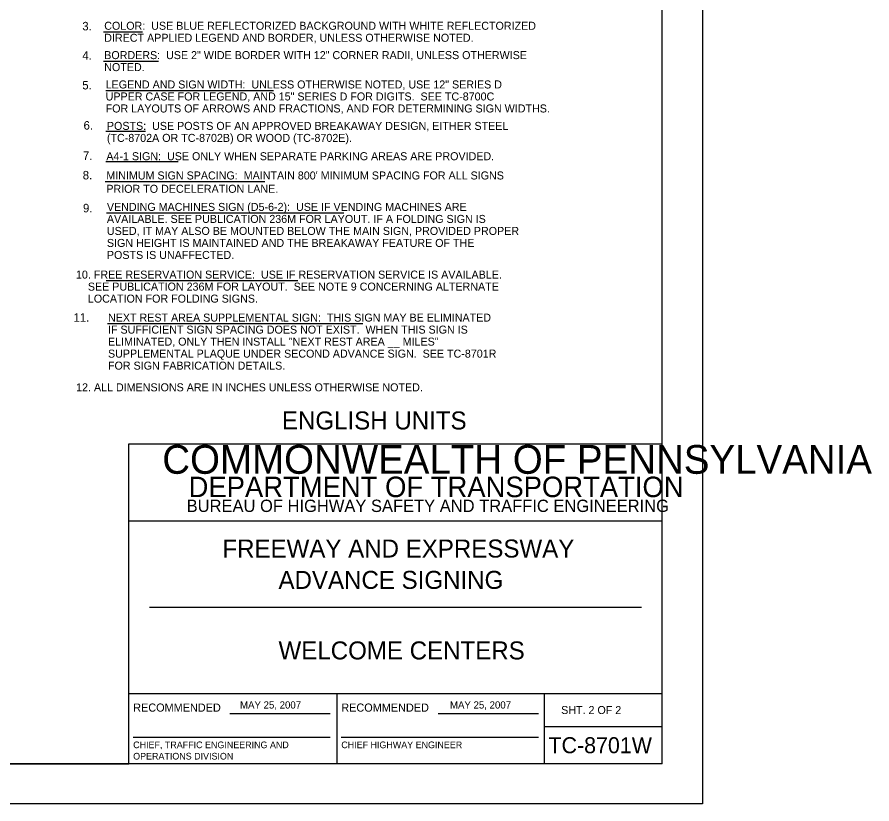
# Model space of a CAD drawing. Extents: x 638689 to 652291, y 298458 to 299646.
# Drawn here: x 651970.5 to 652290.9, y 298457.7 to 298752.7 of the extents above; entities that cross this region are included whole.
import ezdxf

# ---------------------------------------------------------------- set-up
doc = ezdxf.new("R2010")
doc.units = 0
for name, color, linetype in [('1', 7, 'Continuous'), ('2', 7, 'Continuous'), ('PLT-BNDY', 7, 'Continuous')]:
    doc.layers.add(name, color=color, linetype=linetype)

msp = doc.modelspace()

# ---------------------------------------------------------------- linework, layer by layer
at = {"layer": '1'}
for p, q in [((652212.31, 298472.75), (652212.31, 299036.75)), ((652012.31, 298472.75), (652012.31, 298592.75)), ((652012.31, 298592.75), (652212.31, 298592.75)), ((652212.31, 298563.75), (652012.31, 298563.75)), ((652020.06, 298531.43), (652204.56, 298531.43)), ((652012.31, 298499.12), (652212.31, 298499.12)), ((652090.31, 298499.12), (652090.31, 298472.75)), ((652168.19, 298472.75), (652168.19, 298499.12)), ((652050.24, 298491.69), (652087.87, 298491.69)), ((652128.24, 298491.69), (652165.87, 298491.69)), ((652168.19, 298486.75), (652212.31, 298486.75)), ((652013.99, 298482.8), (652087.87, 298482.8)), ((652091.99, 298482.8), (652165.87, 298482.8)), ((652212.31, 298472.75), (651426.31, 298472.75)), ((651426.31, 298472.75), (652012.31, 298472.75))]:
    msp.add_line(p, q, dxfattribs=at)
at = {"layer": '2'}
for p, q in [((652002.92, 298747.19), (652017.54, 298747.19)), ((652002.9, 298736.19), (652023.44, 298736.19)), ((652003.76, 298725.15), (652066.64, 298725.15)), ((652003.76, 298709.96), (652018.61, 298709.96)), ((652003.78, 298698.49), (652030.86, 298698.49)), ((652003.52, 298691.03), (652063.3, 298691.03)), ((652004.01, 298679.24), (652092.98, 298679.24)), ((652003.84, 298653.98), (652075.64, 298653.98)), ((652004.36, 298637.82), (652100.07, 298637.82))]:
    msp.add_line(p, q, dxfattribs=at)
at = {"layer": 'PLT-BNDY'}
msp.add_lwpolyline([(651386.31, 299051.75), (652227.31, 299051.75), (652227.31, 298457.75), (651386.31, 298457.75)], close=True, dxfattribs=at)

# ---------------------------------------------------------------- texts
at = {"layer": '1'}
for s, height, p in [('COMMONWEALTH OF PENNSYLVANIA', 10.7828, (652024.9, 298581.48)), ('DEPARTMENT OF TRANSPORTATION', 7.6837, (652034.76, 298572.73)), ('BUREAU OF HIGHWAY SAFETY AND TRAFFIC ENGINEERING', 4.6253, (652034.04, 298567.16)), ('FREEWAY AND EXPRESSWAY', 6.75, (652047.42, 298550.09)), ('ADVANCE SIGNING', 6.75, (652068.45, 298538.34)), ('WELCOME CENTERS', 6.75, (652068.47, 298511.9)), ('RECOMMENDED', 3.048, (652013.99, 298492.32)), ('RECOMMENDED', 3.048, (652091.99, 298492.32)), ('SHT. 2 OF 2', 3, (652174.4, 298491.43)), ('TC-8701W', 6, (652169.64, 298476.75)), ('CHIEF, TRAFFIC ENGINEERING AND', 2.5, (652013.99, 298478.63)), ('CHIEF HIGHWAY ENGINEER', 2.5, (652091.99, 298478.63)), ('OPERATIONS DIVISION', 2.5, (652013.99, 298474.38))]:
    msp.add_text(s, height=height, dxfattribs=at).set_placement(p)
at = {"layer": '2'}
for s, height, p in [('3.  ', 3.183, (651994.92, 298747.68)), ('COLOR:  USE BLUE REFLECTORIZED BACKGROUND WITH WHITE REFLECTORIZED', 3, (652003.14, 298747.91)), ('DIRECT APPLIED LEGEND AND BORDER, UNLESS OTHERWISE NOTED.', 3, (652003.14, 298743.41)), ('4.  ', 3.183, (651994.92, 298736.67)), ('BORDERS:  USE 2" WIDE BORDER WITH 12" CORNER RADII, UNLESS OTHERWISE ', 3, (652003.14, 298736.91)), ('NOTED.', 3, (652003.14, 298732.41)), ('5.  ', 3.183, (651994.92, 298725.55)), ('LEGEND AND SIGN WIDTH:  UNLESS OTHERWISE NOTED, USE 12" SERIES D', 3, (652003.67, 298725.91)), ('UPPER CASE FOR LEGEND, AND 15" SERIES D FOR DIGITS.  SEE TC-8700C', 3, (652003.67, 298721.41)), ('FOR LAYOUTS OF ARROWS AND FRACTIONS, AND FOR DETERMINING SIGN WIDTHS.', 3, (652003.67, 298716.91)), ('6.  ', 3.183, (651995.39, 298710.49)), ('POSTS:  USE POSTS OF AN APPROVED BREAKAWAY DESIGN, EITHER STEEL', 3, (652004.14, 298710.38)), ('(TC-8702A OR TC-8702B) OR WOOD (TC-8702E).', 3, (652004.14, 298705.88)), ('7.  ', 3.183, (651995.17, 298699.15)), ('A4-1 SIGN:  USE ONLY WHEN SEPARATE PARKING AREAS ARE PROVIDED.', 3, (652003.93, 298699.01)), ('8.  ', 3.183, (651995.09, 298691.81)), ("MINIMUM SIGN SPACING:  MAINTAIN 800' MINIMUM SPACING FOR ALL SIGNS", 3, (652003.93, 298691.8)), ('PRIOR TO DECELERATION LANE.', 3, (652003.93, 298686.8)), ('9.', 3.183, (651995.17, 298679.48)), ('VENDING MACHINES SIGN (D5-6-2):  USE IF VENDING MACHINES ARE', 3, (652004.14, 298680.01)), ('AVAILABLE. SEE PUBLICATION 236M FOR LAYOUT. IF A FOLDING SIGN IS', 3, (652004.14, 298675.51)), ('USED, IT MAY ALSO BE MOUNTED BELOW THE MAIN SIGN, PROVIDED PROPER', 3, (652004.14, 298671.01)), ('SIGN HEIGHT IS MAINTAINED AND THE BREAKAWAY FEATURE OF THE', 3, (652004.14, 298666.51)), ('POSTS IS UNAFFECTED.', 3, (652004.14, 298662.01)), ('10. FREE RESERVATION SERVICE:  USE IF RESERVATION SERVICE IS AVAILABLE.', 3, (651992.55, 298654.64)), ('    SEE PUBLICATION 236M FOR LAYOUT.  SEE NOTE 9 CONCERNING ALTERNATE', 3, (651992.55, 298650.14)), ('    LOCATION FOR FOLDING SIGNS.', 3, (651992.55, 298645.64)), ('11.', 3.183, (651991.61, 298638.46)), ('NEXT REST AREA SUPPLEMENTAL SIGN:  THIS SIGN MAY BE ELIMINATED', 3, (652004.55, 298638.52)), ('IF SUFFICIENT SIGN SPACING DOES NOT EXIST.  WHEN THIS SIGN IS', 3, (652004.55, 298634.02)), ('ELIMINATED, ONLY THEN INSTALL "NEXT REST AREA __ MILES" ', 3, (652004.55, 298629.52)), ('SUPPLEMENTAL PLAQUE UNDER SECOND ADVANCE SIGN.  SEE TC-8701R', 3, (652004.55, 298625.02)), ('FOR SIGN FABRICATION DETAILS.', 3, (652004.55, 298620.52)), ('12. ALL DIMENSIONS ARE IN INCHES UNLESS OTHERWISE NOTED.', 3, (651992.59, 298612.39)), ('ENGLISH UNITS', 6.75, (652069.74, 298598.09)), ('MAY 25, 2007', 2.7, (652054.04, 298493.49)), ('MAY 25, 2007', 2.7, (652132.73, 298493.49))]:
    msp.add_text(s, height=height, dxfattribs=at).set_placement(p)

doc.saveas('drawing.dxf')
